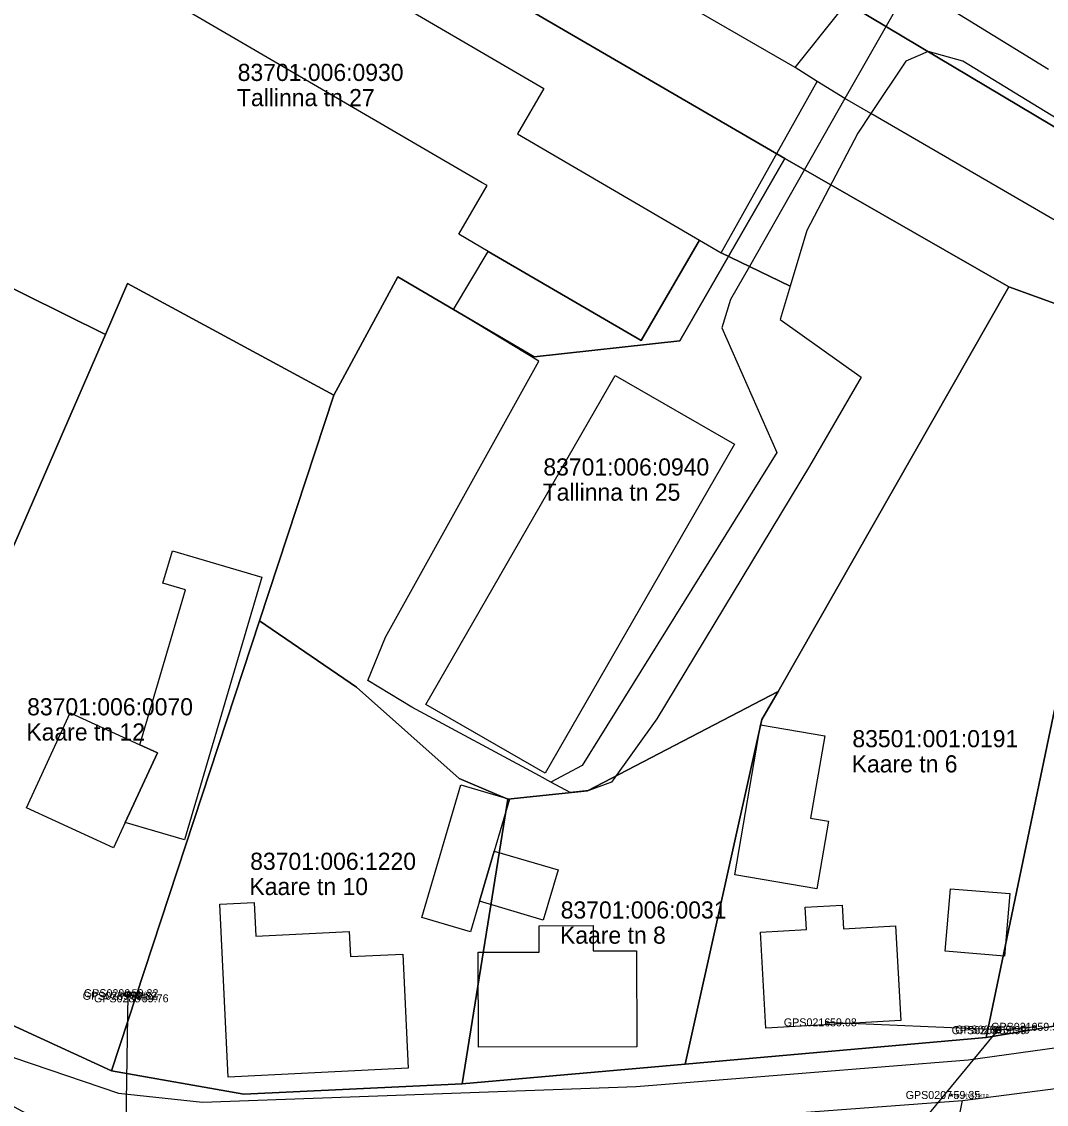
# Model space of a CAD drawing. Extents: x 580119 to 583377, y 6518915 to 6520820.
# Drawn here: x 581623.1 to 581712.7, y 6519732.9 to 6519827.6 of the extents above; entities that cross this region are included whole.
import ezdxf

# ---------------------------------------------------------------- set-up
doc = ezdxf.new("R2010")
doc.units = 0
for name, color, linetype in [('Hoone Elu- või ühiskondlik hoone', 7, 'Continuous'), ('Hoone Kõrval- või tootmishoone', 7, 'Continuous'), ('L_AADRESS', 7, 'Continuous'), ('MAAMUDEL', 7, 'Continuous'), ('MOOTKORG-EH2000', 7, 'Continuous'), ('MOOTMPUNKT', 7, 'Continuous'), ('MOOTNR', 7, 'Continuous'), ('MPOHULIIN', 7, 'Continuous'), ('PIIR', 7, 'Continuous'), ('POST', 7, 'Continuous'), ('SIOHULIIN', 7, 'Continuous'), ('Tee Kergliiklustee Püsikate', 7, 'Continuous'), ('Tee Liiklusala', 7, 'Continuous'), ('Tee Muu', 7, 'Continuous'), ('Tee Tugimaantee Püsikate', 7, 'Continuous'), ('Tee Tänav Püsikate', 7, 'Continuous'), ('TUNNUS', 7, 'Continuous')]:
    doc.layers.add(name, color=color, linetype=linetype)

msp = doc.modelspace()

# ---------------------------------------------------------------- linework, layer by layer
at = {"layer": 'Hoone Elu- või ühiskondlik hoone'}
for points in [[(581682.388, 6519808.483), (581677.263, 6519799.707), (581663.909, 6519807.497), (581661.322, 6519809.006), (581663.806, 6519813.259), (581663.373, 6519813.511), (581631.555, 6519832.085), (581636.522, 6519840.589), (581668.768, 6519821.752), (581666.448, 6519817.783)], [(581685.447, 6519790.63), (581668.875, 6519761.838), (581658.432, 6519767.849), (581675.004, 6519796.64)], [(581632.158, 6519757.532), (581631.139, 6519755.314), (581623.513, 6519758.82), (581627.338, 6519767.136), (581633.429, 6519764.339), (581634.966, 6519763.633)], [(581643.444, 6519750.53), (581643.583, 6519747.584), (581651.754, 6519747.983), (581651.854, 6519745.804), (581656.428, 6519746.019), (581656.905, 6519736.028), (581641.161, 6519735.264), (581640.438, 6519750.379)], [(581687.71, 6519747.932), (581691.74, 6519748.162), (581691.63, 6519750.122), (581694.86, 6519750.292), (581694.98, 6519748.232), (581699.52, 6519748.482), (581699.98, 6519740.201), (581688.17, 6519739.551)], [(581673.072, 6519748.514), (581673.076, 6519746.312), (581676.873, 6519746.316), (581676.89, 6519737.894), (581663.048, 6519737.865), (581663.022, 6519746.19), (581668.361, 6519746.199), (581668.359, 6519748.505)]]:
    msp.add_lwpolyline(points, close=True, dxfattribs=at)
at = {"layer": 'Hoone Kõrval- või tootmishoone'}
for points in [[(581644.114, 6519779.004), (581637.348, 6519756.012), (581632.158, 6519757.532), (581634.966, 6519763.633), (581633.429, 6519764.339), (581637.425, 6519777.892), (581635.46, 6519778.475), (581636.292, 6519781.31)], [(581693.658, 6519757.649), (581692.643, 6519751.73), (581685.469, 6519752.96), (581687.716, 6519766.065), (581693.327, 6519765.103), (581692.096, 6519757.917)], [(581658.105, 6519749.229), (581661.501, 6519760.826), (581665.768, 6519759.576), (581664.43, 6519755.018), (581663.145, 6519750.642), (581662.355, 6519747.972)], [(581670.01, 6519753.376), (581668.713, 6519748.995), (581663.145, 6519750.642), (581664.43, 6519755.018)], [(581709.509, 6519751.307), (581709.042, 6519745.838), (581703.862, 6519746.282), (581704.323, 6519751.741)]]:
    msp.add_lwpolyline(points, close=True, dxfattribs=at)
at = {"layer": 'MOOTMPUNKT'}
for centre in [(581632.354, 6519742.371), (581632.459, 6519742.597), (581633.344, 6519742.148), (581693.532, 6519740.045), (581708.347, 6519739.361), (581708.662, 6519739.414), (581711.663, 6519739.657), (581704.328, 6519733.692)]:
    msp.add_circle(centre, 0.1, dxfattribs=at)
at = {"layer": 'MPOHULIIN'}
msp.add_line((581708.505, 6519739.387), (581693.532, 6519740.045), dxfattribs=at)
msp.add_lwpolyline([(581699.78, 6519728.814), (581708.505, 6519739.387), (581711.663, 6519739.657)], dxfattribs=at)
at = {"layer": 'PIIR'}
for points in [[(582014.36, 6519714.4), (581954.58, 6519728.06), (581945.07, 6519730.21), (581944.37, 6519727.29), (581898.97, 6519737.29), (581899.66, 6519740.22), (581848.58, 6519751.11), (581827.48, 6519756.43), (581810.2, 6519762.82), (581785.83, 6519775.2), (581761.13, 6519789.94), (581562.34, 6519908.5)], [(581562.34, 6519908.5), (581761.13, 6519789.94), (581756.15, 6519781.82), (581745.87, 6519787.29), (581720.78, 6519800.28), (581709.44, 6519804.4), (581689.84, 6519815.63), (581631.91, 6519849.33)], [(581457.82, 6519837.71), (581487.37, 6519818.42), (581513.81, 6519802.22), (581529.53, 6519792.85), (581544.38, 6519782.68), (581569.92, 6519768.18), (581588.17, 6519757.81), (581607.16, 6519746.74), (581630.96, 6519735.8), (581642.52, 6519733.76), (581661.62, 6519734.67), (581681.12, 6519736.39), (581707.45, 6519738.72), (581736.84, 6519743.64)]]:
    msp.add_lwpolyline(points, dxfattribs=at)
for points in [[(581631.91, 6519849.33), (581689.84, 6519815.63), (581680.66, 6519799.67), (581667.91, 6519798.29), (581655.99, 6519805.27), (581650.4, 6519794.91), (581632.37, 6519804.68), (581630.43, 6519800.22), (581612.65, 6519809.04), (581608.97, 6519810.82)], [(581689.84, 6519815.63), (581709.44, 6519804.4), (581689.26, 6519769), (581672.57, 6519760.29), (581665.61, 6519759.57), (581661.35, 6519761.37), (581652.37, 6519769.36), (581643.89, 6519775.17), (581650.4, 6519794.91), (581655.99, 6519805.27), (581667.91, 6519798.29), (581680.66, 6519799.67)], [(581612.65, 6519809.04), (581630.43, 6519800.22), (581607.16, 6519746.74), (581588.17, 6519757.81)], [(581630.43, 6519800.22), (581632.37, 6519804.68), (581650.4, 6519794.91), (581643.89, 6519775.17), (581630.96, 6519735.8), (581607.16, 6519746.74)], [(581707.45, 6519738.72), (581681.12, 6519736.39), (581687.82, 6519766.55), (581689.26, 6519769), (581709.44, 6519804.4), (581720.78, 6519800.28), (581718.64, 6519792.38)], [(581720.78, 6519800.28), (581745.87, 6519787.29), (581736.84, 6519743.64), (581707.45, 6519738.72), (581718.64, 6519792.38)], [(581630.96, 6519735.8), (581643.89, 6519775.17), (581652.37, 6519769.36), (581661.35, 6519761.37), (581665.61, 6519759.57), (581661.62, 6519734.67), (581642.52, 6519733.76)], [(581665.61, 6519759.57), (581672.57, 6519760.29), (581689.26, 6519769), (581687.82, 6519766.55), (581681.12, 6519736.39), (581661.62, 6519734.67)]]:
    msp.add_lwpolyline(points, close=True, dxfattribs=at)
at = {"layer": 'POST'}
for centre in [(581632.407, 6519742.484), (581708.505, 6519739.387)]:
    msp.add_circle(centre, 0.25, dxfattribs=at)
at = {"layer": 'SIOHULIIN'}
msp.add_lwpolyline([(581667.384, 6519727.325), (581632.166, 6519725.646), (581632.407, 6519742.484)], dxfattribs=at)
at = {"layer": 'Tee Kergliiklustee Püsikate'}
for points in [[(581695.095, 6519820.876), (581692.683, 6519822.378), (581690.756, 6519823.578), (581633.141, 6519856.854), (581631.502, 6519857.8)], [(581756.768, 6519785.074), (581697.366, 6519819.557), (581695.095, 6519820.876)]]:
    msp.add_lwpolyline(points, dxfattribs=at)
at = {"layer": 'Tee Liiklusala'}
for points in [[(581458.715, 6519828.549), (581489.684, 6519811.114), (581511.663, 6519798.807), (581527.767, 6519789.883), (581560.664, 6519771.877), (581622.468, 6519736.934), (581631.563, 6519733.84), (581638.915, 6519733.067), (581676.838, 6519734.428), (581705.86, 6519736.754), (581784.648, 6519747.72)], [(581748.242, 6519797.942), (581705.4, 6519824.156), (581702.384, 6519824.977), (581700.431, 6519824.139), (581697.366, 6519819.557), (581696.229, 6519817.858), (581691.778, 6519809.323), (581690.312, 6519804.461), (581686.742, 6519806.188), (581684.271, 6519807.383), (581692.683, 6519822.378), (581690.756, 6519823.578), (581694.565, 6519828.374)]]:
    msp.add_lwpolyline(points, dxfattribs=at)
at = {"layer": 'Tee Muu'}
msp.add_lwpolyline([(581684.271, 6519807.383), (581686.742, 6519806.188), (581690.312, 6519804.461), (581689.429, 6519801.531), (581696.529, 6519796.501), (581691.99, 6519788.72), (581678.656, 6519766.61), (581674.688, 6519761.064), (581672.707, 6519760.334), (581671.059, 6519760.166), (581669.364, 6519761.048), (581668.38, 6519761.602), (581657.23, 6519767.631), (581653.38, 6519769.954), (581654.906, 6519773.746), (581668.334, 6519797.906), (581660.87, 6519802.43), (581663.909, 6519807.497), (581677.263, 6519799.707), (581682.388, 6519808.483)], close=True, dxfattribs=at)
at = {"layer": 'Tee Tugimaantee Püsikate'}
msp.add_lwpolyline([(581700.796, 6519830.9), (581712.911, 6519823.436)], dxfattribs=at)
at = {"layer": 'Tee Tänav Püsikate'}
for points in [[(581700.796, 6519830.9), (581695.095, 6519820.876)], [(581695.095, 6519820.876), (581686.742, 6519806.188), (581685.097, 6519803.295), (581684.325, 6519800.824), (581689.15, 6519789.892), (581672.128, 6519762.514), (581669.364, 6519761.048)], [(581705.381, 6519733.197), (581730.904, 6519736.516), (581781.788, 6519744.093), (581797.73, 6519746.692), (581808.192, 6519752.253), (581811.442, 6519754.035), (581814.375, 6519755.992)], [(581611.37, 6519738.642), (581624.23, 6519731.701), (581632.918, 6519729.777), (581646.462, 6519729.392), (581671.806, 6519730.709), (581705.381, 6519733.197)], [(581666.474, 6519649.427), (581701.13, 6519722.484), (581704.617, 6519729.447), (581705.381, 6519733.197)]]:
    msp.add_lwpolyline(points, dxfattribs=at)

# ---------------------------------------------------------------- texts
at = {"layer": 'L_AADRESS'}
for s, p in [('Tallinna tn 27', (581641.929, 6519820.207)), ('Tallinna tn 25', (581668.663, 6519785.687)), ('Kaare tn 12', (581623.517, 6519764.702)), ('Kaare tn 6', (581695.687, 6519761.913)), ('Kaare tn 10', (581643.022, 6519751.184)), ('Kaare tn 8', (581670.177, 6519746.926))]:
    msp.add_text(s, height=1.5, dxfattribs=at).set_placement(p)
at = {"layer": 'MAAMUDEL'}
for s, p in [(' kilp', (581632.459, 6519742.422)), (' kaabel', (581632.459, 6519742.422)), (' kilp', (581632.354, 6519742.196)), (' kaabel', (581632.354, 6519742.196)), (' mp_ohl', (581633.344, 6519741.973)), (' mp_ohl8.15mp', (581704.328, 6519733.517))]:
    msp.add_text(s, height=0.35, dxfattribs=at).set_placement(p)
at = {"layer": 'MOOTKORG-EH2000'}
for s, p in [(' 59.82', (581632.354, 6519742.021)), (' 59.82', (581632.459, 6519742.247)), (' 59.76', (581633.344, 6519741.798)), (' 59.08', (581693.532, 6519739.695)), (' 59.52', (581711.663, 6519739.307)), (' 59.39', (581708.347, 6519739.011)), (' 59.45', (581708.662, 6519739.064)), (' 59.35', (581704.328, 6519733.342))]:
    msp.add_text(s, height=0.7, dxfattribs=at).set_placement(p)
at = {"layer": 'MOOTNR'}
for s, p in [('GPS0289 ', (581628.435, 6519742.021)), ('GPS0290 ', (581628.539, 6519742.247)), ('GPS0288 ', (581629.424, 6519741.798)), ('GPS0216 ', (581689.753, 6519739.695)), ('GPS0210 ', (581707.884, 6519739.307)), ('GPS0208 ', (581704.427, 6519739.011)), ('GPS0209 ', (581704.743, 6519739.064)), ('GPS0207 ', (581700.408, 6519733.342))]:
    msp.add_text(s, height=0.7, dxfattribs=at).set_placement(p)
at = {"layer": 'TUNNUS'}
for s, p in [('83701:006:0930', (581641.993, 6519822.412)), ('83701:006:0940', (581668.726, 6519787.892)), ('83701:006:0070', (581623.58, 6519766.907)), ('83501:001:0191', (581695.75, 6519764.118)), ('83701:006:1220', (581643.085, 6519753.389)), ('83701:006:0031', (581670.24, 6519749.131))]:
    msp.add_text(s, height=1.5, dxfattribs=at).set_placement(p)

doc.saveas('drawing.dxf')
